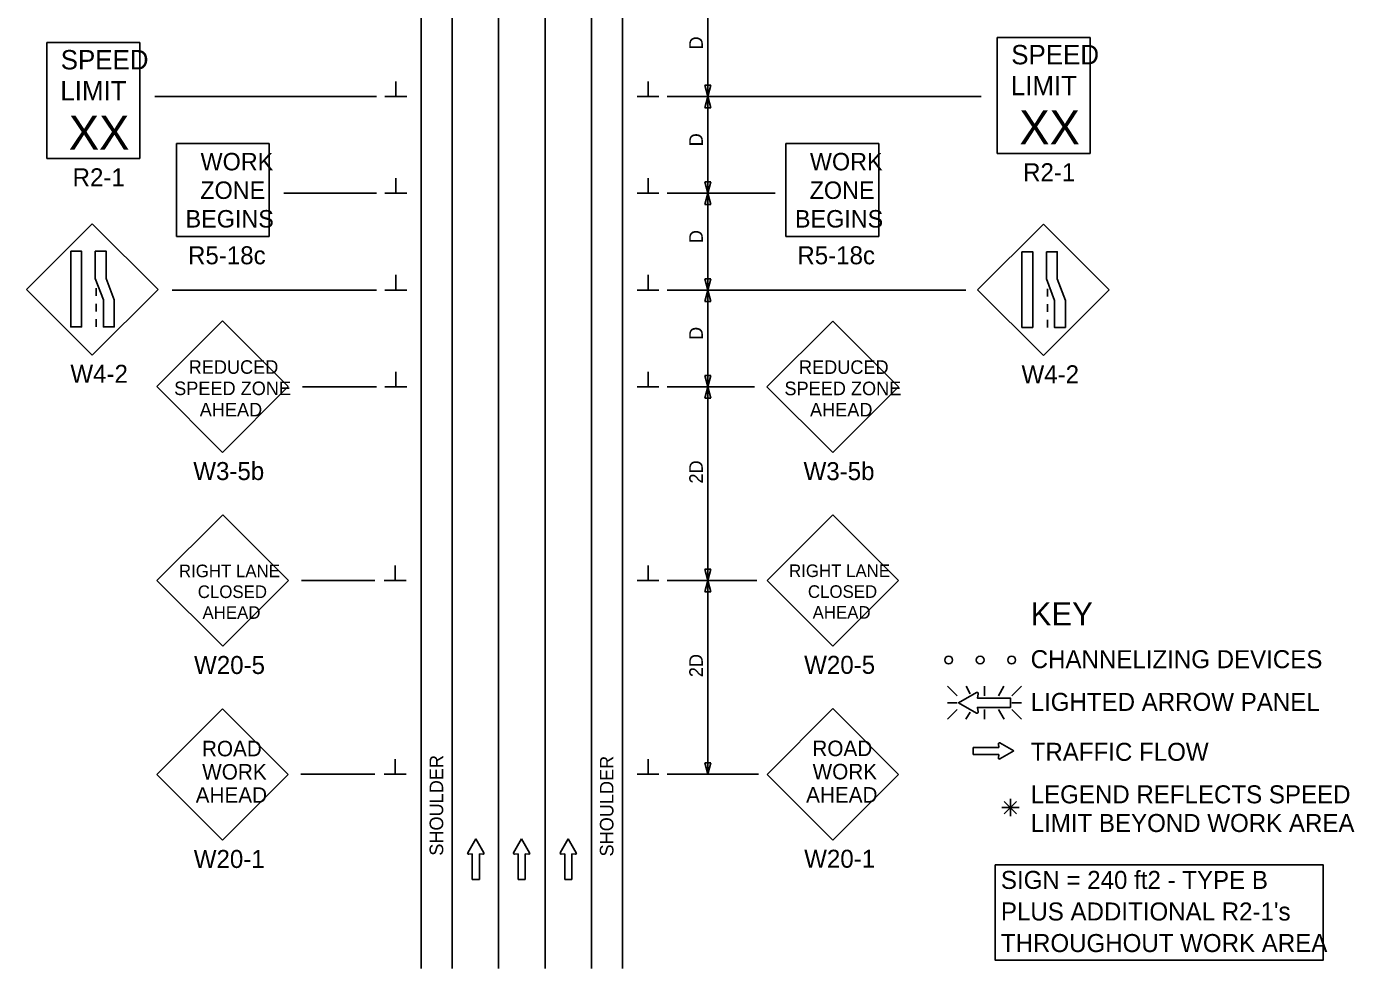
# Model space of a CAD drawing. Extents: x 16734 to 18479, y 5690 to 6927.
# Drawn here: x 16747 to 17433, y 6108 to 6594 of the extents above; entities that cross this region are included whole.
import ezdxf

# ---------------------------------------------------------------- set-up
doc = ezdxf.new("R2010")
doc.units = 0
for name, color, linetype in [('ALI_LEGAL_EX', 7, 'Continuous'), ('BORDER', 7, 'Continuous'), ('Level 10', 7, 'Continuous'), ('SCRATCH_LEVEL_A', 7, 'Continuous'), ('TRAFFIC_SIGNS_PR', 7, 'Continuous'), ('TYPICAL_TEXT_DIMEN_EX', 7, 'Continuous')]:
    doc.layers.add(name, color=color, linetype=linetype)

msp = doc.modelspace()

# ---------------------------------------------------------------- linework, layer by layer
at = {"layer": 'ALI_LEGAL_EX'}
for p, q in [((16991.15, 6924.81), (16991.15, 6107.83)), ((17015.15, 6924.81), (17015.15, 6107.83))]:
    msp.add_line(p, q, dxfattribs=at)
for points in [[(16991.15, 6524.81), (16991.15, 6499.81)], [(17015.15, 6524.81), (17015.15, 6499.81)], [(16991.15, 6474.81), (16991.15, 6449.81)], [(17015.15, 6474.81), (17015.15, 6449.81)], [(16991.15, 6424.81), (16991.15, 6399.81)], [(17015.15, 6424.81), (17015.15, 6399.81)], [(16991.15, 6324.81), (16991.15, 6299.81)], [(17015.15, 6324.81), (17015.15, 6299.81)], [(16991.15, 6224.81), (16991.15, 6199.81)], [(17015.15, 6224.81), (17015.15, 6199.81)], [(16991.15, 6124.81), (16991.15, 6107.83)], [(17015.15, 6124.81), (17015.15, 6107.83)]]:
    msp.add_lwpolyline(points, dxfattribs=at)
at = {"layer": 'BORDER'}
for p, q in [((16757.79, 6586.05), (16805.79, 6586.05)), ((16757.79, 6526.05), (16757.79, 6586.05)), ((16805.79, 6526.05), (16805.79, 6586.05)), ((17248.63, 6588.68), (17296.63, 6588.68)), ((17248.63, 6528.68), (17248.63, 6588.68)), ((17296.63, 6528.68), (17296.63, 6588.68)), ((16824.72, 6485.79), (16824.72, 6533.79)), ((16824.72, 6533.79), (16872.72, 6533.79)), ((16872.72, 6485.79), (16872.72, 6533.79)), ((17139.39, 6485.79), (17139.39, 6533.79)), ((17139.39, 6533.79), (17187.39, 6533.79)), ((17187.39, 6485.79), (17187.39, 6533.79)), ((17248.63, 6528.68), (17296.63, 6528.68)), ((16757.79, 6526.05), (16805.79, 6526.05)), ((16781.3, 6492.46), (16747.36, 6458.52)), ((16815.24, 6458.52), (16781.3, 6492.46)), ((17272.45, 6492.19), (17238.51, 6458.25)), ((17306.39, 6458.25), (17272.45, 6492.19)), ((16824.72, 6485.79), (16872.72, 6485.79)), ((17139.39, 6485.79), (17187.39, 6485.79)), ((16747.36, 6458.52), (16781.3, 6424.58)), ((16781.3, 6424.58), (16815.24, 6458.52)), ((16783.35, 6459.13), (16783.35, 6455.13)), ((17238.51, 6458.25), (17272.45, 6424.31)), ((17272.45, 6424.31), (17306.39, 6458.25)), ((17274.5, 6458.86), (17274.5, 6454.86)), ((16783.35, 6451.13), (16783.35, 6447.13)), ((17274.5, 6450.86), (17274.5, 6446.86)), ((16783.35, 6443.13), (16783.35, 6439.13)), ((16848.52, 6442.24), (16814.58, 6408.3)), ((16882.46, 6408.3), (16848.52, 6442.24)), ((17163.67, 6442.19), (17129.72, 6408.25)), ((17197.61, 6408.25), (17163.67, 6442.19)), ((17274.5, 6442.86), (17274.5, 6438.86)), ((16814.58, 6408.3), (16848.52, 6374.36)), ((16848.52, 6374.36), (16882.46, 6408.3)), ((17129.72, 6408.25), (17163.67, 6374.3)), ((17163.67, 6374.3), (17197.61, 6408.25)), ((16848.64, 6342.08), (16814.7, 6308.13)), ((16882.58, 6308.13), (16848.64, 6342.08)), ((17163.7, 6342.16), (17129.76, 6308.21)), ((17197.64, 6308.21), (17163.7, 6342.16)), ((16814.7, 6308.13), (16848.64, 6274.19)), ((16848.64, 6274.19), (16882.58, 6308.13)), ((17129.76, 6308.21), (17163.7, 6274.27)), ((17163.7, 6274.27), (17197.64, 6308.21)), ((17222.94, 6253.54), (17227.87, 6248.61)), ((17234.7, 6249.72), (17232.5, 6253.55)), ((17242.02, 6248.61), (17242.02, 6253.55)), ((17249.26, 6248.61), (17252.11, 6253.55)), ((17256.17, 6248.61), (17261.11, 6253.55)), ((16848.5, 6241.9), (16814.56, 6207.96)), ((16882.44, 6207.96), (16848.5, 6241.9)), ((17163.72, 6242.01), (17129.78, 6208.07)), ((17197.66, 6208.07), (17163.72, 6242.01)), ((17227.87, 6245.06), (17222.94, 6245.06)), ((17222.94, 6236.57), (17227.87, 6241.5)), ((17232.45, 6236.57), (17234.56, 6240.23)), ((17242.02, 6241.5), (17242.02, 6236.57)), ((17252.15, 6236.57), (17249.3, 6241.5)), ((17256.17, 6245.06), (17261.11, 6245.06)), ((17256.17, 6241.5), (17261.11, 6236.56)), ((16814.56, 6207.96), (16848.5, 6174.02)), ((16848.5, 6174.02), (16882.44, 6207.96)), ((17129.78, 6208.07), (17163.72, 6174.13)), ((17163.72, 6174.13), (17197.66, 6208.07))]:
    msp.add_line(p, q, dxfattribs=at)
for points in [[(16770.18, 6478.19), (16770.18, 6439.13), (16775.8, 6439.13), (16775.8, 6478.19)], [(16782.85, 6478.19), (16782.85, 6464.21), (16787.03, 6453.11), (16787.03, 6439.13), (16792.65, 6439.13), (16792.65, 6453.11), (16788.47, 6464.21), (16788.47, 6478.19)], [(17261.33, 6477.92), (17261.33, 6438.86), (17266.95, 6438.86), (17266.95, 6477.92)], [(17274, 6477.92), (17274, 6463.94), (17278.18, 6452.84), (17278.18, 6438.86), (17283.8, 6438.86), (17283.8, 6452.84), (17279.62, 6463.94), (17279.62, 6477.92)]]:
    msp.add_lwpolyline(points, close=True, dxfattribs=at)
for points in [[(17237.95, 6250.33), (17228.66, 6245.06), (17237.95, 6239.73)], [(17238.83, 6240.36), (17238.42, 6242.63), (17255.44, 6242.63), (17255.44, 6247.43), (17238.42, 6247.43), (17238.83, 6249.71)]]:
    msp.add_lwpolyline(points, dxfattribs=at)
for centre in [(17223.5, 6267.09), (17239.8, 6267.09), (17256.1, 6267.09)]:
    msp.add_circle(centre, 2, dxfattribs=at)
for centre, radius, start, end in [((17238.24, 6249.81), 0.598, 350.73078, 118.89165), ((17238.24, 6240.26), 0.597, 241.48329, 9.95933)]:
    msp.add_arc(centre, radius, start, end, dxfattribs=at)
at = {"layer": 'Level 10'}
for p, q in [((17249.52, 6222.01), (17236.26, 6222.01)), ((17236.26, 6222.01), (17236.26, 6218.27)), ((17249.21, 6223.79), (17249.52, 6222.01)), ((17257.13, 6220.16), (17249.89, 6224.27)), ((17249.89, 6216.01), (17257.13, 6220.16)), ((17236.26, 6218.27), (17249.52, 6218.27)), ((17249.52, 6218.27), (17249.21, 6216.49)), ((16979.3, 6174.71), (16975.19, 6167.47)), ((16983.44, 6167.47), (16979.3, 6174.71)), ((17003, 6174.71), (16998.89, 6167.47)), ((17007.15, 6167.47), (17003, 6174.71)), ((17027.11, 6174.71), (17023, 6167.47)), ((17031.26, 6167.47), (17027.11, 6174.71)), ((16975.67, 6166.78), (16977.45, 6167.1)), ((16977.45, 6167.1), (16977.45, 6153.84)), ((16981.19, 6153.84), (16981.19, 6167.1)), ((16981.19, 6167.1), (16982.97, 6166.78)), ((16999.37, 6166.78), (17001.15, 6167.1)), ((17001.15, 6167.1), (17001.15, 6153.84)), ((17004.89, 6153.84), (17004.89, 6167.1)), ((17004.89, 6167.1), (17006.67, 6166.78)), ((17023.48, 6166.78), (17025.26, 6167.1)), ((17025.26, 6167.1), (17025.26, 6153.84)), ((17029, 6153.84), (17029, 6167.1)), ((17029, 6167.1), (17030.78, 6166.78)), ((16977.45, 6153.84), (16981.19, 6153.84)), ((17001.15, 6153.84), (17004.89, 6153.84)), ((17025.26, 6153.84), (17029, 6153.84))]:
    msp.add_line(p, q, dxfattribs=at)
for centre, start, end in [((17249.66, 6223.86), 60.42484, 189.96381), ((17249.66, 6216.42), 170.03619, 299.77312), ((16975.59, 6167.24), 150.42484, 279.96381), ((16983.04, 6167.25), 260.03619, 29.77312), ((16999.3, 6167.24), 150.42484, 279.96381), ((17006.74, 6167.25), 260.03619, 29.77312), ((17023.41, 6167.24), 150.42484, 279.96381), ((17030.85, 6167.25), 260.03619, 29.77312)]:
    msp.add_arc(centre, 0.463, start, end, dxfattribs=at)
at = {"layer": 'SCRATCH_LEVEL_A'}
for p, q in [((16951.15, 6927.15), (16951.15, 6107.83)), ((16967.15, 6927.15), (16967.15, 6107.83)), ((17039.15, 6927.15), (17039.15, 6107.83)), ((17055.15, 6927.15), (17055.15, 6107.83))]:
    msp.add_line(p, q, dxfattribs=at)
at = {"layer": 'TRAFFIC_SIGNS_PR'}
for p, q in [((17099.15, 6608.18), (17099.15, 6558.18)), ((16938.03, 6558.18), (16938.03, 6565.97)), ((17068.28, 6558.18), (17068.28, 6565.97)), ((17099.15, 6558.18), (17097.58, 6564.04)), ((17097.58, 6564.04), (17099.15, 6564.04)), ((17099.15, 6564.04), (17100.72, 6564.04)), ((17100.72, 6564.04), (17099.15, 6558.18)), ((16813.56, 6558.18), (16928.15, 6558.18)), ((16932.4, 6558.18), (16943.65, 6558.18)), ((17073.9, 6558.18), (17062.65, 6558.18)), ((17240.31, 6558.18), (17078.15, 6558.18)), ((17097.58, 6552.32), (17099.15, 6558.18)), ((17099.15, 6558.18), (17099.15, 6508.18)), ((17099.15, 6558.18), (17100.72, 6552.32)), ((17099.15, 6552.32), (17097.58, 6552.32)), ((17100.72, 6552.32), (17099.15, 6552.32)), ((16938.03, 6508.18), (16938.03, 6515.97)), ((17068.28, 6508.18), (17068.28, 6515.97)), ((16880.24, 6508.18), (16928.15, 6508.18)), ((16932.4, 6508.18), (16943.65, 6508.18)), ((17073.9, 6508.18), (17062.65, 6508.18)), ((17133.97, 6508.18), (17078.15, 6508.18)), ((17099.15, 6508.18), (17097.58, 6514.04)), ((17097.58, 6514.04), (17099.15, 6514.04)), ((17097.58, 6502.32), (17099.15, 6508.18)), ((17099.15, 6514.04), (17100.72, 6514.04)), ((17100.72, 6514.04), (17099.15, 6508.18)), ((17099.15, 6508.18), (17099.15, 6458.18)), ((17099.15, 6508.18), (17100.72, 6502.32)), ((17099.15, 6502.32), (17097.58, 6502.32)), ((17100.72, 6502.32), (17099.15, 6502.32)), ((16938.03, 6458.18), (16938.03, 6465.97)), ((17068.28, 6458.18), (17068.28, 6465.97)), ((17099.15, 6458.18), (17097.58, 6464.04)), ((17097.58, 6464.04), (17099.15, 6464.04)), ((17099.15, 6464.04), (17100.72, 6464.04)), ((17100.72, 6464.04), (17099.15, 6458.18)), ((16822.53, 6458.18), (16928.15, 6458.18)), ((16932.4, 6458.18), (16943.65, 6458.18)), ((17073.9, 6458.18), (17062.65, 6458.18)), ((17232.38, 6458.18), (17078.15, 6458.18)), ((17097.58, 6452.32), (17099.15, 6458.18)), ((17099.15, 6458.18), (17099.15, 6408.18)), ((17099.15, 6458.18), (17100.72, 6452.32)), ((17099.15, 6452.32), (17097.58, 6452.32)), ((17100.72, 6452.32), (17099.15, 6452.32)), ((16938.03, 6408.18), (16938.03, 6415.97)), ((17068.28, 6408.18), (17068.28, 6415.97)), ((17099.15, 6408.18), (17097.58, 6414.04)), ((17097.58, 6414.04), (17099.15, 6414.04)), ((17099.15, 6414.04), (17100.72, 6414.04)), ((17100.72, 6414.04), (17099.15, 6408.18)), ((16889.8, 6408.18), (16928.15, 6408.18)), ((16932.4, 6408.18), (16943.65, 6408.18)), ((17073.9, 6408.18), (17062.65, 6408.18)), ((17123.34, 6408.18), (17078.15, 6408.18)), ((17097.58, 6402.32), (17099.15, 6408.18)), ((17099.15, 6408.18), (17099.15, 6308.18)), ((17099.15, 6408.18), (17100.72, 6402.32)), ((17099.15, 6402.32), (17097.58, 6402.32)), ((17100.72, 6402.32), (17099.15, 6402.32)), ((16937.74, 6308.18), (16937.74, 6315.97)), ((17068.28, 6308.18), (17068.28, 6315.97)), ((17099.15, 6308.18), (17097.58, 6314.04)), ((17097.58, 6314.04), (17099.15, 6314.04)), ((17099.15, 6314.04), (17100.72, 6314.04)), ((17100.72, 6314.04), (17099.15, 6308.18)), ((16927.29, 6308.18), (16889.42, 6308.18)), ((16943.36, 6308.18), (16932.11, 6308.18)), ((17073.9, 6308.18), (17062.65, 6308.18)), ((17124.5, 6308.18), (17078.15, 6308.18)), ((17097.58, 6302.32), (17099.15, 6308.18)), ((17099.15, 6302.32), (17097.58, 6302.32)), ((17099.15, 6308.18), (17099.15, 6208.18)), ((17099.15, 6308.18), (17100.72, 6302.32)), ((17100.72, 6302.32), (17099.15, 6302.32)), ((16937.74, 6208.18), (16937.74, 6215.97)), ((17068.28, 6208.18), (17068.28, 6215.97)), ((17099.15, 6208.18), (17097.58, 6214.04)), ((17097.58, 6214.04), (17099.15, 6214.04)), ((17099.15, 6214.04), (17100.72, 6214.04)), ((17100.72, 6214.04), (17099.15, 6208.18)), ((16927.29, 6208.18), (16889.03, 6208.18)), ((16943.36, 6208.18), (16932.11, 6208.18)), ((17073.9, 6208.18), (17062.65, 6208.18)), ((17125.27, 6208.18), (17078.15, 6208.18)), ((17252.28, 6194.1), (17258.65, 6187.73)), ((17258.65, 6194.1), (17252.28, 6187.73)), ((17255.46, 6190.91), (17255.46, 6195.37)), ((17255.46, 6190.91), (17250.93, 6190.91)), ((17255.46, 6190.91), (17258.65, 6190.91)), ((17255.46, 6190.91), (17259.94, 6190.91)), ((17255.46, 6190.91), (17255.46, 6186.41))]:
    msp.add_line(p, q, dxfattribs=at)
at = {"layer": 'TYPICAL_TEXT_DIMEN_EX'}
msp.add_lwpolyline([(17247.5, 6161.3), (17416.95, 6161.3), (17416.95, 6112.11), (17247.5, 6112.11)], close=True, dxfattribs=at)

# ---------------------------------------------------------------- texts
at = {"layer": 'BORDER'}
for s, height, p in [('SPEED', 10, (17255.84, 6574.76)), ('SPEED', 10, (16765, 6572.13)), ('LIMIT', 10, (16764.8, 6556.13)), ('LIMIT', 10, (17255.63, 6558.76)), ('XX', 17.538, (17260.02, 6533.38)), ('XX', 17.538, (16769.18, 6530.75)), ('WORK', 9.021, (16837.22, 6520)), ('WORK', 9.021, (17151.89, 6520)), ('R2-1', 9.3, (16771.14, 6511.76)), ('R2-1', 9.3, (17261.97, 6514.38)), ('ZONE', 9.021, (16837.07, 6505.24)), ('ZONE', 9.021, (17151.74, 6505.24)), ('BEGINS', 9.021, (16829.48, 6490.47)), ('BEGINS', 9.021, (17144.15, 6490.47)), ('R5-18c', 9.3, (16830.73, 6471.49)), ('R5-18c', 9.3, (17145.4, 6471.49)), ('W4-2', 9.3, (16770, 6410.28)), ('REDUCED', 7, (16831.09, 6414.93)), ('REDUCED', 7, (17146.24, 6414.88)), ('W4-2', 9.3, (17261.15, 6410.01)), ('SPEED ZONE', 7, (16823.58, 6403.93)), ('SPEED ZONE', 7, (17138.73, 6403.88)), ('AHEAD', 7, (16836.78, 6392.93)), ('AHEAD', 7, (17151.93, 6392.88)), ('W3-5b', 9.3, (16833.46, 6360.05)), ('W3-5b', 9.3, (17148.61, 6360)), ('RIGHT LANE', 6.5, (16826.04, 6309.88)), ('RIGHT LANE', 6.5, (17141.11, 6309.96)), ('CLOSED', 6.5, (16835.78, 6299.13)), ('CLOSED', 6.5, (17150.85, 6299.21)), ('AHEAD', 6.5, (17153.28, 6288.46)), ('AHEAD', 6.5, (16838.21, 6288.38)), ('W20-5', 9.3, (16833.86, 6259.9)), ('W20-5', 9.3, (17148.92, 6259.98)), ('ROAD', 8, (16837.93, 6217.38)), ('ROAD', 8, (17153.15, 6217.49)), ('WORK', 8, (16838.06, 6205.38)), ('WORK', 8, (17153.28, 6205.49)), ('AHEAD', 8, (16834.7, 6193.38)), ('AHEAD', 8, (17149.92, 6193.49)), ('W20-1', 9.3, (16833.71, 6159.72)), ('W20-1', 9.3, (17148.93, 6159.83))]:
    msp.add_text(s, height=height, dxfattribs=at).set_placement(p)
at = {"layer": 'TRAFFIC_SIGNS_PR'}
for s, p in [('D', (17096.59, 6582.4)), ('D', (17096.59, 6532.4)), ('D', (17096.59, 6482.4)), ('D', (17096.59, 6432.4)), ('2D', (17096.59, 6358.26)), ('2D', (17096.59, 6258.26)), ('SHOULDER', (16962.51, 6166.05)), ('SHOULDER', (17050.43, 6165.64))]:
    msp.add_text(s, height=7, rotation=90, dxfattribs=at).set_placement(p)
at = {"layer": 'TYPICAL_TEXT_DIMEN_EX'}
for s, height, p in [('KEY', 12, (17265.88, 6284.95)), ('CHANNELIZING DEVICES', 9.3, (17265.88, 6262.9)), ('LIGHTED ARROW PANEL', 9.3, (17265.88, 6240.85)), ('TRAFFIC FLOW', 9.3, (17265.88, 6215.05)), ('LEGEND REFLECTS SPEED', 9.3, (17265.88, 6193.1)), ('LIMIT BEYOND WORK AREA', 9.3, (17265.88, 6178.3)), ('SIGN = 240 ft2 - TYPE B', 9.3, (17250.51, 6148.9)), ("PLUS ADDITIONAL R2-1's", 9.3, (17250.51, 6132.6)), ('THROUGHOUT WORK AREA', 9.3, (17250.51, 6116.3))]:
    msp.add_text(s, height=height, dxfattribs=at).set_placement(p)

doc.saveas('drawing.dxf')
